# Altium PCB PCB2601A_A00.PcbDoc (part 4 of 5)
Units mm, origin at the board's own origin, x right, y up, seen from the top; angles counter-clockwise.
Board outline 30.4 x 51 mm, 8 copper layers (Top Layer, Signal Layer 2, Signal Layer 3, Signal Layer 4, Signal Layer 5, Signal Layer 6, Signal Layer 7, Bottom Layer), stack 1.492 mm thick; 194 components, 130 nets, 5039 pads, 478 vias.
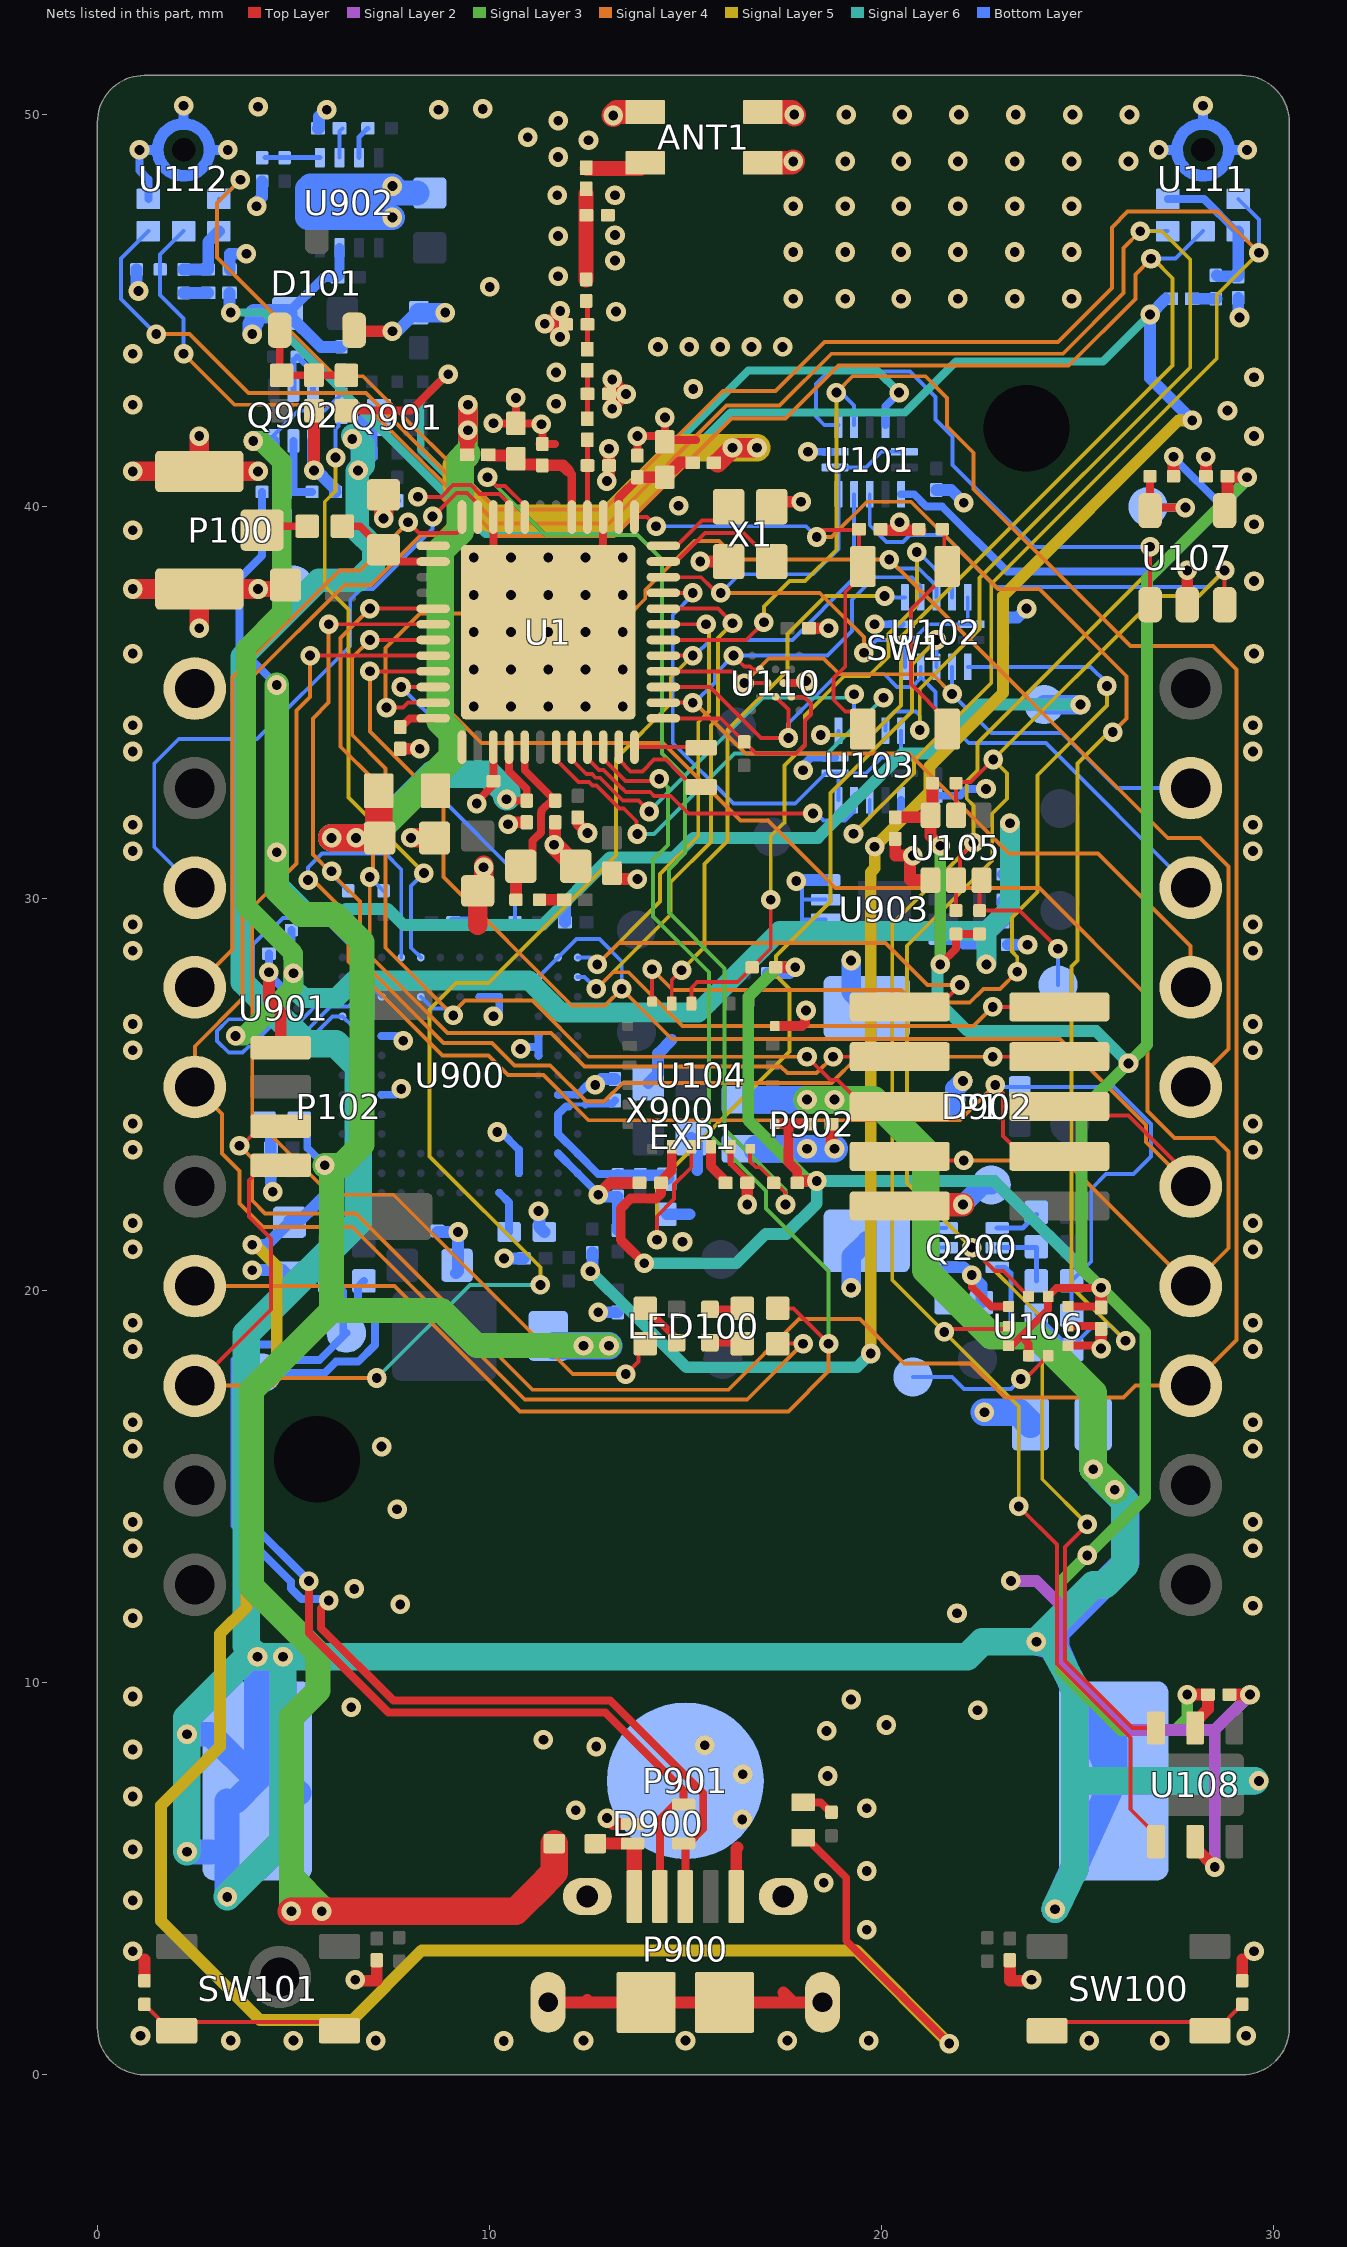
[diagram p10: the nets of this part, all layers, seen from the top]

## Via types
v1: diameter 0.5, hole 0.25, Top Layer to Bottom Layer, tented both sides, 478 vias

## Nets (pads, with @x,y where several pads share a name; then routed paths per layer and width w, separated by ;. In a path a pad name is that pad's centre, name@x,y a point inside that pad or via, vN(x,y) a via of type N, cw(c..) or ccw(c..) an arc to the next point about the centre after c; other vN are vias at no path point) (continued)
DBG_3V3: C914.1 C919.1 Q902.3 R906.2 R910.2 R911.2 R912.2 R929.2 R933.1 U901.A1 U901.E3 U903.8 | length 50.8
  Signal Layer 3 w0.5: v1(3.525,26.5) 3.75,26.5 5,27.75 v1(5,28.101) 5,28.6 3.8,29.8 3.8,36.4 4.7,37.3 4.7,41.15 4.175,41.675 v1(3.975,41.675)
  Signal Layer 6 w0.508: v1(5,28.101) 5,27.725 5.253,27.472 6.097,27.472 6.538,27.913 11.012,27.913 11.825,27.1 12.575,27.1 12.575,27.096 12.975,27.096 12.979,27.1 13.121,27.1 13.125,27.096 13.625,27.096 13.629,27.1 15.325,27.1 17.4,29.175 22.675,29.175 ; v1@22.675,28.35 22.675,29.175 ; v1(23.275,31.925) 23.275,29.775 22.675,29.175
  Bottom Layer w0.1: Q902.3@4.5,41.675 4.5,41.825 5.125,42.45 5.8,42.45 R929.2@6.225,42.875 R933.1@6.225,43.475
  Bottom Layer w0.2: C919.1@22.675,28.85 22.675,28.925 23.1,29.35 R912.2@23.1,29.4
  Bottom Layer w0.203: v1(3.525,26.5) 4.1,26.5 U901.E3@4.4,26.8 ; C914.1@4.925,28.6 4.963,28.562 4.963,28.139 v1(5,28.101) ; C914.1@4.945,28.625 4.95,28.63 R906.2@4.95,29.2 ; v1@5.025,28.126 5.1,28.052 U901.A1@5.1,27.6
  Bottom Layer w0.3: v1(3.975,41.675) Q902.3@4.5,41.675 ; U903.8@21.575,28.975 21.975,28.975 22.1,28.85 C919.1@22.525,28.85 ; v1(22.675,28.325) C919.1@22.675,28.825 ; R912.2@23.1,29.4 R911.2@23.1,29.95 ; R910.2@23.1,30.625 23.275,30.8 v1(23.275,31.925)
DBG_SPI_CS: R906.1 U900.B1 U900.B2 U901.A3 | length 5.6
  Bottom Layer w0.1: R906.1@4.35,29.1 4.36,29.1 4.469,29.209 R906.1@4.469,29.219 ; U901.A3@4.4,27.6 4.4,27.605 4.286,27.719 4.207,27.719 3.969,27.957 3.969,28.829 4.34,29.2 R906.1@4.35,29.2 4.459,29.309 4.534,29.309 4.737,29.512 5.738,29.512 U900.B1@6.75,28.5 U900.B2@6.75,28
DBG_SPI_MISO: U900.A4 U900.B3 U901.C3 | length 7.2
  Bottom Layer w0.1: U901.C3@4.4,27.2 4.125,26.925 3.35,26.925 3.05,26.625 3.05,26.375 3.35,26.075 3.7,26.075 3.85,26.225 5.225,26.225 6,27 U900.A4@6.25,27 6.5,26.75 6.925,26.75 7,26.825 7,27.25 U900.B3@6.75,27.5
DBG_SPI_MOSI: U900.C3 U901.D2 | length 3.6
  Bottom Layer w0.1: U901.D2@4.75,27 4.75,26.7 4.925,26.525 5.225,26.525 5.95,27.25 6.4,27.25 6.5,27.35 6.5,27.625 6.625,27.75 7,27.75 U900.C3@7.25,27.5
DBG_SPI_SCLK: U900.A3 U901.E1 | length 1.4
  Bottom Layer w0.1: U901.E1@5.1,26.8 5.8,27.5 U900.A3@6.25,27.5
DBG_USB_DM: D900.5 P900.2 R903.1 TPJ19.1 | length 26.8
  Top Layer w0.203: v1(5.395,12.595) 5.395,11.274 7.424,9.245 12.955,9.245 14.95,7.25 D900.5@14.95,6.9 14.725,6.9 14.345,6.52 P900.2@14.345,4.55
  Bottom Layer w0.203: v1(5.395,12.595) 3.805,14.186 3.805,17.505 TPJ19.1@4.2,17.9 5.797,17.9 6.088,18.191 6.652,18.191 7.079,18.618 7.079,19.222 6.642,19.659 6.642,20.092 R903.1@6.8,20.25
DBG_USB_DP: D900.4 P900.3 R904.1 TPJ18.1 | length 27.7
  Top Layer w0.203: v1(5.9,12.1) 5.7,11.9 5.7,11.4 7.55,9.55 13.081,9.55 15.453,7.178 15.453,6.278 15.075,5.9 D900.4@14.95,5.9 14.995,5.855 P900.3@14.995,4.55
  Bottom Layer w0.203: v1(5.9,12.1) 5.86,12.14 5.206,12.14 4.94,12.406 4.94,12.579 3.5,14.019 3.5,17.608 3.498,17.609 3.498,18.191 3.5,18.192 3.5,18.23 3.898,18.629 4.502,18.629 4.9,18.23 5.66,18.23 TPJ18.1@6.35,18.92 6.271,18.92 6.271,19.979 R904.1@6,20.25
DBG_VBUS: C901.1 D901.2 L901.2 R917.2 TPJ12.1 U900.A11 U900.B12 | length 86.7
  Top Layer w0.7: v1(4.95,4.175) v1(5.725,4.175) 10.675,4.175 11.42,4.92 11.42,4.933 11.65,5.163 L901.2@11.65,5.9
  Signal Layer 3 w0.635: v1(4.575,35.45) v1(4.575,31.183) 4.575,30.225 5.2,29.6 6.05,29.6 6.75,28.9 6.75,23.725 6.225,23.2 v1(5.8,23.2) ; v1(4.95,4.175) v1(5.725,4.175) ; v1@4.95,4.275 4.95,5.05 ; v1@5.725,4.275 4.95,5.05 ; v1@5.975,23.025 5.975,19.5 ; v1(13.05,18.6) v1(12.4,18.6) 9.675,18.6 8.775,19.5 5.975,19.5 ; 4.95,5.05 4.95,9.125 5.625,9.8 5.625,10.758 3.928,12.455 3.928,17.454 5.975,19.5
  Signal Layer 6 w0.305: v1(4.575,31.183) 4.575,30.542 5.538,29.578 6.178,29.578 6.339,29.739 7.402,29.739 7.816,29.325 11.35,29.325 13.075,31.05 14.7,31.05 15.2,31.55 18.375,31.55 20.525,33.7 21.275,33.7 22.525,34.95 v1(25.075,34.95)
  Bottom Layer w0.152: v1(5.8,23.2) 5.95,23.2 U900.A11@6.25,23.5 U900.B12@6.75,23
  Bottom Layer w0.2: R917.2@4.2,40.375 4.2,38.75 3.625,38.175 3.625,36.4 v1(4.575,35.45) ; C901.1@5.15,24.3 5.355,24.095 5.355,23.645 v1(5.8,23.2)
  Bottom Layer w0.5: TPJ12.1@24.15,34.95 v1(25.075,34.95)
  Bottom Layer w0.7: D901.2@11.65,18.6 v1(12.4,18.6) v1(13.05,18.6)
DBG_VREGO: C902.1 LED900.1 U900.A12 | length 51.6
  Top Layer w0.2: LED900.1@18,6.05 18.075,6.05 19.1,5.025 19.1,3.425 v1(21.726,0.799)
  Signal Layer 5 w0.3: v1@4,21.2 4.575,20.625 4.575,18.3 3.805,17.53 3.805,11.93 3.125,11.25 3.125,8.375 1.625,6.875 1.625,3.925 4.15,1.4 6.5,1.4 8.275,3.175 19.35,3.175 v1(21.726,0.799)
  Bottom Layer w0.2: 5.85,22.475 5.85,22.6 U900.A12@6.25,23
  Bottom Layer w0.3: v1(3.95,21.175) 4.325,21.175 C902.1@4.9,21.75 ; C902.1@4.9,21.8 5.175,21.8 5.4,22.025 5.407,22.025 5.7,22.318 5.7,22.325 5.85,22.475
DEBUG_PTI_DATA: P1.10 U1.7 U900.N1 | length 23.3
  Top Layer w0.1: U1.7@14.435,37 15.5,37 15.525,36.975 v1(15.525,37)
  Top Layer w0.102: P1.10@20.465,27.24 21.44,27.24 v1(22,27.8)
  Signal Layer 4 w0.1: v1(12.75,28.325) 13.3,28.875 20.1,28.875 21.175,27.8 v1(22,27.8)
  Signal Layer 5 w0.1: v1(12.75,28.325) 14.35,29.925 14.35,30.625 15.325,31.6 15.325,34.5 15.6,34.775 15.6,36.925 v1(15.525,37)
  Bottom Layer w0.1: U900.N1@12.25,28.5 12.575,28.5 v1(12.75,28.325)
DEBUG_PTI_FRAME: P1.9 U1.8 U900.N2 | length 26
  Top Layer w0.1: U1.8@14.435,37.4 15.825,37.4 v1(16.2,37.025) ; v1(22.835,27.24) P1.9@24.535,27.24
  Signal Layer 4 w0.1: v1(12.725,27.7) 13.15,28.125 13.55,28.125 14.925,26.75 22.345,26.75 v1(22.835,27.24)
  Signal Layer 5 w0.1: v1(12.725,27.7) 14.625,29.6 14.625,30.425 15.65,31.45 15.65,34.425 15.825,34.6 15.825,36.65 v1(16.2,37.025)
  Bottom Layer w0.1: U900.N2@12.25,28 12.425,28 v1(12.725,27.7)
DEBUG_RESET: D902.1 P1.3 R206.1 R209.1 U900.D1 | length 39.9
  Top Layer w0.1: v1(22.9,25.25) 23.1,25.05 23.1,23.95 23.62,23.43 P1.3@24.535,23.43
  Signal Layer 4 w0.1: v1(5.375,30.475) 5.5,30.475 6.4,29.575 6.4,28.4 8.8,26 9.975,26 10.475,25.5 11.375,25.5 12.525,24.35 22,24.35 v1(22.9,25.25)
  Bottom Layer w0.1: v1(5.375,30.475) 5.375,30.8 5.725,31.15 7.35,31.15 7.75,30.75 U900.D1@7.75,28.5 ; v1(22.9,25.25) 22.95,25.2 D902.1@23.525,25.2 25.925,25.2 26.875,24.25 26.875,23.425 26.425,22.975 25.725,22.975 25.35,22.6 25.35,20.75 R206.1@24.85,20.25 R209.1@24.85,19.4
DEBUG_SWCLK: P1.8 R920.2 U1.29 | length 26.6
  Top Layer w0.1: v1(6.95,37.4) U1.29@8.565,37.4 ; v1(18.765,25.97) P1.8@20.465,25.97
  Signal Layer 4 w0.1: v1(6.95,37.4) 6.2,36.65 6.2,33.875 7.025,33.05 7.025,30.632 v1(6.946,30.554) 6.946,28.554 8.925,26.575 11.575,26.575 12.425,25.725 17.425,25.725 17.6,25.55 18.345,25.55 v1(18.765,25.97)
  Bottom Layer w0.1: v1(6.946,30.554) R920.2@7.3,30.2
DEBUG_SWDIO: P1.7 R919.2 U1.30 | length 32.3
  Top Layer w0.1: v1(5.9,37) U1.30@8.565,37 ; v1(22.835,25.97) P1.7@24.535,25.97
  Signal Layer 4 w0.1: v1(5.9,37) 5.9,35 5.5,34.6 5.5,31.125 5.975,30.65 6.7,29.925 6.7,28.45 8.825,26.325 10.064,26.325 10.639,25.75 11.55,25.75 12.475,24.825 12.925,24.825 13.4,25.3 18.725,25.3 19.395,25.97 v1(22.835,25.97)
  Bottom Layer w0.1: v1@5.975,30.65 5.975,30.625 R919.2@6.4,30.2
  other v1: 5.975,30.7
DEBUG_SWO: P1.6 U1.31 U900.E3 | length 26.3
  Top Layer w0.1: v1@6.825,36.6 U1.31@8.565,36.6 ; v1(18.1,25.97) 18.695,25.375 18.875,25.375 19.55,24.7 P1.6@20.465,24.7
  Signal Layer 4 w0.1: v1(6.95,36.6) 6.5,36.15 6.5,34.175 7.35,33.325 7.35,28.75 v1@9.037,27.063 ; v1(9.075,27.025) v1@9.037,27.063 ; v1(18.1,25.97) 12.53,25.97 11.094,27.406 9.381,27.406 v1@9.037,27.063
  Bottom Layer w0.1: U900.E3@8.25,27.5 8.555,27.195 8.905,27.195 v1(9.075,27.025)
EFR32_AIN0: C130.1 R129.2 U1.26 | length 2.7
  Top Layer w0.2: R129.2@6.25,39.5 6.7,39.5 C130.1@7.3,38.9 7.6,38.6 U1.26@8.565,38.6
EFR32_AIN1: U1.25
EFR32_AIN2: EXP1.7 U1.24 | length 16.2
  Top Layer w0.1: v1(7.925,39.6) 8.2,39.325 9.175,39.325 9.3,39.45 U1.24@9.3,39.735
  Signal Layer 4 w0.1: EXP1.7@2.486,27.74 3.45,28.704 3.45,35.65 6.175,38.375 6.7,38.375 v1(7.925,39.6)
EFR32_AIN3: EXP1.5 U1.23 | length 16
  Top Layer w0.1: v1@8.556,39.744 9.163,40.35 9.425,40.35 9.7,40.075 U1.23@9.7,39.735
  Bottom Layer w0.1: EXP1.5@2.486,30.28 1.45,31.316 1.45,33.45 2.075,34.075 4.075,34.075 6.45,36.45 6.45,37.625 6.725,37.9 7.025,37.9 8.55,39.425 v1(8.55,39.75)
EFR32_PA04: R135.2 U1.32 | length 28.7
  Top Layer w0.1: v1(5.425,36.2) U1.32@8.565,36.2 ; v1(13.475,17.875) 13.8,18.2 13.8,18.45 R135.2@14,18.65
  Signal Layer 4 w0.1: v1(5.425,36.2) 5.425,35.15 5.075,34.8 5.075,30.9 3.95,29.775 3.95,24.45 5.95,22.45 7.55,22.45 12.125,17.875 v1(13.475,17.875)
EFR32_PA05: EXP1.12 P1.5 U1.33 U900.L2 U900.M1 | length 38.4
  Top Layer w0.1: v1(6.95,35.8) U1.33@8.565,35.8 ; P1.5@24.535,24.7 25.5,24.7 25.725,24.475 26.071,24.475 26.3,24.475 27.886,22.889 EXP1.12@27.886,22.66
  Signal Layer 4 w0.1: v1(6.95,35.8) 6.95,34.263 8.825,32.388 8.825,30.55 12.1,27.275 12.95,27.275 v1(13.375,27.7) 14.65,26.425 24.55,26.425 26.75,24.225 26.75,23.796 EXP1.12@27.886,22.66
  Bottom Layer w0.1: U900.L2@11.25,28 U900.M1@11.75,28.5 12.218,28.968 12.807,28.968 13.375,28.4 v1(13.375,27.7)
EFR32_PA06: EXP1.14 P1.4 R921.2 U1.34 | length 48.4
  Top Layer w0.1: v1(7.75,35.4) U1.34@8.565,35.4
  Top Layer w0.102: P1.4@20.465,23.43 20.57,23.325 v1(22.1,23.325)
  Signal Layer 4 w0.1: v1(7.75,35.4) 8.375,35.4 9.8,33.975 14.425,33.975 16.4,32 17.1,32 18.825,30.275 24.025,30.275 26.788,27.512 26.788,24.587 27.475,23.9 28.5,23.9 28.85,23.55 28.85,21.084 EXP1.14@27.886,20.12 24.681,23.325 v1(22.1,23.325)
  Bottom Layer w0.102: v1(7.75,35.4) 8.8,34.35 8.8,32.525 10.65,30.675 R921.2@10.65,29.4
EFR32_PA07: EXP1.10 U1.35 U102.10 | length 36.8
  Top Layer w0.1: v1(7.375,34.875) 7.8,34.875 7.925,35 U1.35@8.565,35
  Signal Layer 4 w0.1: v1(7.375,34.875) 7.35,34.9 7.35,36.4 8.225,37.275 13.6,37.275 13.975,37.65 13.975,37.875 15.225,39.125 15.85,39.125 16.325,38.65 v1(20.2,38.65) 27.3,31.55 28.125,31.55 28.85,30.825 28.85,26.164 EXP1.10@27.886,25.2
  Bottom Layer w0.1: v1(20.2,38.65) 20.425,38.425 20.95,38.425 21.4,37.975 U102.10@21.4,37.685
EFR32_PB00: EXP1.9 R136.2 U1.21 | length 43.3
  Top Layer w0.1: v1(8.175,40.25) 8.775,40.25 9.075,40.55 9.525,40.55 9.75,40.325 10.25,40.325 10.5,40.075 U1.21@10.5,39.735 ; R136.2@17.35,18.65 v1(18,18.65)
  Signal Layer 4 w0.1: v1(8.175,40.25) 8.775,40.25 9.075,39.95 9.075,39.65 8.7,39.275 8.25,39.275 6.975,38 6.3,38 3.9,35.6 3.9,30.175 3.7,29.975 3.7,27.45 2.486,26.236 EXP1.9@2.486,25.2 3.175,24.511 3.175,23.5 3.625,23.05 3.625,22.225 4.225,21.625 6.5,21.625 10.9,17.225 16.575,17.225 v1(18,18.65)
EFR32_PB01: R103.2 U1.20 U104.12 | length 26.8
  Top Layer w0.1: v1(9.95,40.75) 10.175,40.525 10.4,40.525 10.9,40.025 U1.20@10.9,39.735 ; U104.12@16.65,23.625 16.65,23.3 16.8,23.15 16.9,23.15 17.55,22.5 v1(17.55,22.2)
  Signal Layer 3 w0.1: v1(9.95,40.75) 11.425,39.275 13.775,39.275 14.4,38.65 14.4,33.7 14.988,33.112 14.988,31.163 14.575,30.75 14.575,29.65 16,28.225 16,24.125 17.55,22.575 v1(17.55,22.2)
EFR32_PC00: R100.2 U1.1 U110.B4 | length 5.8
  Top Layer w0.1: U1.1@14.435,34.6 15.9,34.6 R100.2@16.5,34 16.8,33.7 17.825,33.7 18.05,33.925 18.05,34.55 18.2,34.7 18.2,34.975 18.025,35.15 U110.B4@17.7,35.15
EFR32_PC01: EXP1.8 U1.2 U102.9 U110.F2 | length 26
  Top Layer w0.1: U1.2@14.435,35 v1@15.235,35 ; v1(16.225,36.2) 16.5,35.925 16.65,35.925 16.725,35.85 U110.F2@16.9,35.85
  Signal Layer 4 w0.1: v1@15.235,35 16.535,33.7 20.7,33.7 23.25,31.15 25.525,31.15 27.886,28.789 EXP1.8@27.886,27.74
  Bottom Layer w0.1: v1@15.235,35 15.75,35.515 15.75,35.725 v1(16.225,36.2) 18.625,36.2 19.25,36.825 19.25,37.625 19.825,38.2 20.775,38.2 21,37.975 U102.9@21,37.685
  other v1: 15.185,35
EFR32_PC02: EXP1.6 U1.3 U102.4 U110.D4 | length 18.9
  Top Layer w0.1: U1.3@14.435,35.4 15.625,35.4 16.925,34.1 v1(17.625,34.1) ; U110.D4@17.3,35.15 17.625,34.825 v1@17.625,34.225
  Bottom Layer w0.1: v1(17.625,34.1) 17.625,34.475 18.875,35.725 20.075,35.725 20.4,35.4 20.775,35.4 21,35.625 U102.4@21,35.65 ; U102.4@21,35.915 U102.4@21,35.65 ; EXP1.6@27.886,30.28 24.191,33.975 22.225,33.975 21.375,34.825 21.375,35.275 U102.4@21,35.65
EFR32_PC03: EXP1.4 U1.4 U102.2 U110.E3 | length 16.5
  Top Layer w0.1: U1.4@14.435,35.8 16.2,35.8 v1(16.5,35.5) U110.E3@17.1,35.5
  Signal Layer 4 w0.1: v1(16.5,35.5) 17.125,36.125 18.525,36.125 18.925,35.725 21.3,35.725 v1(21.8,35.225)
  Bottom Layer w0.1: U102.2@21.8,35.915 v1(21.8,35.225) 22.8,34.225 24.6,34.225 26.005,32.82 EXP1.4@27.886,32.82
EFR32_PC04: EXP1.15 P102.4 U1.5 U101.4 | length 45.4
  Top Layer w0.1: EXP1.15@2.486,17.58 4.425,19.519 4.425,21.334 3.863,21.896 3.863,22.813 4.25,23.2 P102.4@4.675,23.2 ; U1.5@14.435,36.2 v1(15.185,36.2) v1@15.235,36.2
  Signal Layer 4 w0.1: EXP1.15@2.486,17.58 4.48,17.58 4.675,17.775 v1(7.125,17.775)
  Signal Layer 5 w0.1: v1(11.3,20.15) 11.3,20.6 8.475,23.425 8.475,27.175 9.15,27.85 9.975,27.85 13.225,31.1 13.225,33.575 14.625,34.975 14.625,35.64 v1(15.185,36.2)
  Signal Layer 6 w0.1: v1(7.125,17.775) 9.5,20.15 v1(11.3,20.15)
  Bottom Layer w0.1: v1@15.235,36.2 15.635,36.6 17.725,36.6 19.3,38.175 U101.4@19.3,40.315
EFR32_PC05: EXP1.16 P102.3 U1.6 U101.9 | length 74.3
  Top Layer w0.1: v1(3.625,23.7) 3.675,23.7 4.175,24.2 P102.3@4.675,24.2 ; U1.6@14.435,36.6 16.55,36.6 v1(17,37.05)
  Signal Layer 4 w0.1: v1(3.625,23.7) 3.95,23.375 3.95,22.3 4.275,21.975 6.6,21.975 11.1,17.475 16.1,17.475 17.9,19.275 19.45,19.275 20.575,18.15 22.275,18.15 23.15,17.275 26.175,17.275 26.48,17.58 EXP1.16@27.886,17.58 29.05,18.744 29.05,35.85 28.45,36.45 26.35,36.45 22.35,40.45 22.35,41.375 21.675,42.05 21.675,42.775 21.125,43.325 19.265,43.325 v1(18.85,42.91)
  Signal Layer 5 w0.1: v1(17,37.05) 17,37.45 17.65,38.1 18.05,38.1 18.85,38.9 v1(18.85,42.91)
  Bottom Layer w0.1: v1(18.85,42.91) 18.965,42.91 19.3,42.575 U101.9@19.3,42.085
EFR32_PC08: U1.9 U103.5 U103.6 U103.12 U103.13 | length 13.3
  Top Layer w0.1: U1.9@14.435,37.8 v1@15.235,37.8
  Bottom Layer w0.1: v1@15.235,37.8 14.675,37.24 14.675,33.975 16.225,32.425 17.8,32.425 18.575,33.2 U103.6@18.815,33.2 ; U103.5@18.9,32.515 18.9,33.115 U103.6@18.815,33.2 ; U103.12@20.5,34.285 20.5,33.685 U103.13@20.585,33.6 20,33.6 19.6,33.2 U103.6@18.815,33.2
  other v1: 15.185,37.8
EFR32_PC09: U1.10 U101.5 U101.6 U101.13 U102.5 U102.6 U102.12 U102.13 | length 18.1
  Top Layer w0.1: U1.10@14.435,38.2 15.401,38.2 15.635,37.966 ; 15.635,37.965 15.8,37.8 v1(15.9,37.8)
  Signal Layer 4 w0.1: v1(15.9,37.8) 18.425,37.8 19.55,36.675 v1(19.55,36.275)
  Bottom Layer w0.1: v1(15.9,37.8) 16.375,38.275 18.25,38.275 18.9,38.925 U101.5@18.9,40.315 18.9,40.915 U101.6@18.815,41 19.6,41 20,41.4 U101.13@20.585,41.4 ; v1(19.55,36.275) 19.875,36.6 U102.6@20.515,36.6 ; U102.5@20.6,35.915 20.6,36.515 U102.6@20.515,36.6 ; U102.12@22.2,37.685 22.2,37.085 U102.13@22.285,37 21.2,37 20.8,36.6 U102.6@20.515,36.6
EFR32_PD00: U1.48 X2.1 | length 1.7
  Top Layer w0.1: U1.48@13.7,33.865 15.385,33.865 X2.1@15.4,33.85
EFR32_PD01: U1.47 X2.2 | length 3
  Top Layer w0.1: U1.47@13.3,33.865 13.3,33.55 13.6,33.25 13.9,33.25 14.2,33.55 14.5,33.55 14.8,33.25 15.2,32.85 X2.2@15.4,32.85
EFR32_PD02: EXP1.13 R137.2 U1.46 | length 38.8
  Top Layer w0.1: U1.46@12.9,33.865 12.9,33.575 13.468,33.007 14.283,33.007 v1(14.332,33.056) ; R137.2@17.35,19.55 17.75,19.55 v1(18.65,18.65)
  Signal Layer 3 w0.1: v1(14.332,33.056) 14.55,32.838 14.55,31.375 14.175,31 14.175,29.55 15.6,28.125 15.6,24 17.05,22.55 17.05,22.1 18.65,20.5 v1(18.65,18.65)
  Signal Layer 4 w0.1: EXP1.13@2.486,20.12 7.58,20.12 10.775,16.925 17.625,16.925 18.65,17.95 v1(18.65,18.65)
EFR32_PD03: U1.45 U103.4 | length 8.1
  Top Layer w0.1: U1.45@12.5,33.865 12.5,33.577 12.792,33.285 12.907,33.285 13.385,32.807 13.393,32.807 13.476,32.724 14.101,32.724 14.2,32.625 14.625,32.625 15.075,32.175 v1(18.25,32.175)
  Bottom Layer w0.1: v1(18.25,32.175) 18.35,32.175 18.525,32 19.075,32 19.3,32.225 U103.4@19.3,32.515
EFR32_PD04: U1.44 U103.9 | length 10.2
  Top Layer w0.1: U1.44@12.1,33.865 12.1,33.55 12.47,33.18 12.614,33.18 12.709,33.085 12.815,33.085 13.4,32.5 13.8,32.5 v1(14.075,32.225)
  Signal Layer 6 w0.1: v1(14.075,32.225) 16.975,35.125 19.209,35.125 v1(19.3,35.216)
  Bottom Layer w0.1: U103.9@19.3,34.285 v1(19.3,35.216)
EFR32_PD05: U1.43 U103.10 | length 12.1
  Top Layer w0.1: U1.43@11.7,33.865 11.7,33.55 12.275,32.975 12.537,32.975 12.627,32.885 12.732,32.885 13.317,32.3 13.425,32.3 13.75,31.975 v1@13.75,31.65
  Signal Layer 6 w0.1: v1@13.75,31.65 14.2,31.65 16.25,33.7 18.625,33.7 v1(20.05,35.125)
  Bottom Layer w0.1: U103.10@19.7,34.285 19.7,34.775 v1(20.05,35.125)
  other v1: 13.775,31.65
EFR32_RESET: C1.1 R209.2 R212.2 SW1.1 SW1.2 U1.13 | length 43.3
  Top Layer w0.1: U1.13@13.7,39.735 14.015,39.735 v1(14.25,39.5) ; v1(18.35,39.225) 18.525,39.4 19.425,39.4 19.425,38.575 SW1.2@19.525,38.475 19.525,38.275 19.075,37.825 19.075,35.925 18.775,35.625 18.775,35.075 19.075,34.775 19.3,34.775 19.525,34.55 SW1.1@19.525,34.325
  Signal Layer 4 w0.1: v1(18.35,39.225) 18.725,39.225 19.625,40.125 20.75,40.125 22.975,37.9 24.025,37.9 26.25,35.675 26.25,34.6 v1(25.9,34.25)
  Signal Layer 5 w0.102: v1(25.9,34.25) 25.8,34.25 25,33.45 25,28.425 24.85,28.275 24.85,20.1 v1(26.225,18.725)
  Bottom Layer w0.1: v1(14.25,39.5) 18.075,39.5 v1(18.35,39.225) v1@18.425,39.15
  Bottom Layer w0.102: R209.2@23.95,19.4 24.8,18.55 24.85,18.55 25.4,19.1 25.85,19.1 v1(26.225,18.725)
GND: ANT1.2 ANT1.3 ANT1.4 C1.2 C3.2 C4.2 C5.2 C6.2 C7.2 C8.2 C9.2 C11.2 C12.2 C13.2 C14.2 C15.2 C17.2 C18.2 C19.2 C20.2 C21.2 C22.2 C23.2 C24.2 C101.2 C104.2 C105.2 C106.2 C110.2 C111.2 C113.2 C114.2 C115.2 C117.2 C130.2 C142.2 C145.2 C154.2 C156.2 C900.2 C901.2 C902.2 C903.2 C904.2 C905.2 C907.2 C908.2 C909.2 C910.2 C911.2 C914.2 C915.2 C916.2 C917.2 C918.2 C919.2 C920.2 C921.2 C923.2 C924.2 C925.2 C926.2 D101.2 D900.2 D902.3 EXP1.1 P1.2 P100.2 P100.3 P102.1 P900.5 P900.6 P900.7 P900.8 P900.9 P900.10 P900.11 P901.2 P902.1 P902.3 P902.4 Q200.1 Q902.1 R1.1 R141.2 R144.2 R150.2 R208.1 R909.1 R915.1 R916.1 R933.2 TPJ13.1 U1.0 U1.15 U1.22 U1.39 U101.7 U102.7 U103.7 U104.11 U104.18 U105.1 U106.3 U106.8 U106.9 U107.2 U108.2 U110.C3 U111.3 U112.2 U112.3 U900.C5 U900.C8 U900.H3 U900.J3 U900.K11 U900.K12 U900.L5 U900.L6 U900.M8 U900.M11 U900.N8 U900.N12 U901.B2 U902.3 U902.9 U903.1 U903.2 U903.3 U903.4 X1.2 X1.4 X900.2 X900.4 | length 155.3
  Top Layer w0.15: U104.11@16.15,23.747 U104.11@16.15,23.675 16.15,23.25 16.575,22.825 C106.2@16.575,22.8
  Top Layer w0.2: v1(9.675,32.425) 9.675,32.475 10.1,32.9 C9.2@10.1,33 U1.39@10.1,33.865 ; U1.0@10.1,35.4 v1(11.5,36.8) ; U1.22@10.1,39.735 10.1,38.2 v1(10.55,37.75) v1(11.5,36.8) ; v1(10.1,42.125) C18.2@10.675,42.125 ; v1(10.675,42.775) C18.2@10.675,42.125 ; C19.2@11.275,41.6 C19.2@11.35,41.6 ; v1@11.275,42.075 11.225,42.125 C18.2@10.675,42.125 ; v1@11.35,42.075 C19.2@11.35,41.6 ; 11.675,41.6 C19.2@11.35,41.6 ; U1.15@12.9,39.735 12.9,38.2 v1(11.5,36.8) ; C12.2@13.775,41.3 v1(13.775,41.8) ; v1@13.825,41.8 14.325,41.8 C11.2@14.475,41.65 ; v1(14.475,42.275) C11.2@14.475,41.65 ; 15.275,41.7 14.525,41.7 C11.2@14.475,41.65 ; U110.C3@17.5,35.5 18.025,35.5 v1(18.075,35.55) ; v1(22.3,20.4) 22.3,20.1 22.8,19.6 U106.3@23.243,19.6 ; U106.8@24.758,18.6 25.525,18.6 v1(25.6,18.525) ; U106.9@24.758,19.1 25.525,19.1 C111.2@25.6,19.025
  Top Layer w0.203: ANT1.4@13.972,49.978 ANT1.4@13.986,49.978
  Top Layer w0.25: v1@11.453,44.72 11.543,44.72 11.686,44.72 11.756,44.65 11.805,44.65 11.874,44.65 11.805,44.718 v1(11.805,44.991) ; v1(11.799,44.33) 11.799,44.374 11.799,44.388 11.799,44.575 C5.2@11.874,44.649 ; C5.2@11.874,44.65 11.953,44.65 C5.2@11.981,44.65 ; C4.2@13.025,42.87 C4.2@13.132,42.87 ; v1(13.132,42.495) 13.132,42.743 C4.2@13.132,42.87 ; v1(13.132,43.245) 13.132,43.057 13.132,42.978 C4.2@13.132,42.87 ; v1(13.482,42.87) 13.24,42.87 C4.2@13.132,42.87 ; U104.18@17.375,26.75 17.975,26.75 18.05,26.825 18.05,27.125 v1(18.075,27.15)
  Top Layer w0.3: R144.2@1.2,2.4 1.2,2.95 ; v1(4.375,28.125) 4.375,27.4 4.675,27.1 P102.1@4.675,26.2 ; C115.2@5.5,42.45 5.525,42.425 v1(5.525,40.925) ; D101.2@6.55,44.5 6.575,44.475 v1(7.525,44.475) v1@7.575,44.475 ; v1(6.575,2.425) 6.6,2.4 7.125,2.4 C145.2@7.125,2.925 ; C17.2@7.725,33.825 v1(8.225,33.825) ; v1(10.475,31.9) 10.525,31.95 C13.2@10.95,31.95 ; P900.8@11.495,1.85 12.425,1.85 ; v1@11.6,31.425 11.675,31.5 C21.2@11.675,31.95 ; v1@11.756,44.995 v1@11.781,45.02 ; v1(11.799,44.33) 11.843,44.33 11.799,44.374 v1@11.792,44.381 ; v1(11.805,44.991) v1@11.805,44.996 ; C5.2@11.874,44.649 11.874,44.462 11.799,44.388 v1@11.792,44.381 ; C5.2@11.874,44.65 11.874,44.928 11.825,44.976 11.808,44.993 v1@11.805,44.996 ; C15.2@12.25,32.075 12.25,31.925 v1(12.5,31.675) ; 12.495,1.92 12.425,1.85 ; v1(12.776,22.451) 13.075,22.75 C104.2@13.825,22.75 ; v1@13.025,40.675 13.05,40.7 C3.2@13.05,41.05 13.05,41.45 v1@13.075,41.475 ; C4.2@13.025,42.85 13.132,42.743 v1@13.243,42.632 ; C14.2@13.125,30.65 13.275,30.5 v1(13.775,30.5) ; v1@13.167,43.242 13.167,43.185 v1@13.175,43.177 ; C4.2@13.175,42.937 v1@13.175,43.1 ; v1@13.218,43.275 v1@13.175,43.232 ; v1@13.25,42.861 13.24,42.87 13.174,42.936 13.132,42.978 13.125,42.986 13.037,42.898 13.037,42.962 13.132,43.057 v1@13.175,43.1 ; v1@13.25,43.175 v1@13.241,43.166 ; v1@13.327,43.001 13.359,42.97 v1@13.379,42.974 ; v1@13.425,42.982 v1@13.379,42.974 ; v1(13.482,42.87) v1@13.243,42.632 ; v1(13.482,42.87) v1@13.379,42.974 ; v1(15.375,38.6) X1.2@16.1,38.6 ; P900.5@16.295,4.55 16.295,5.77 16.325,5.8 ; v1@16.575,22.25 16.575,22.3 C106.2@16.575,22.75 C106.2@16.575,22.8 ; X1.4@17.2,40 17.325,40.125 v1(17.95,40.125) ; 17.495,2.105 17.75,1.85 ; C101.2@18.15,36.9 v1(18.65,36.9) v1@18.75,36.9 ; P900.9@18.495,1.85 17.75,1.85 ; C105.2@18.725,24.25 18.725,23.7 v1(18.8,23.625) ; C1.2@19.975,39.4 R1.1@21,39.4 ; C110.2@20.35,31.525 20.35,31.1 v1(20.8,31.1) 20.725,31.025 20.725,30.475 U105.1@21.25,30.475 ; C142.2@23.275,2.925 23.275,2.4 23.8,2.4 v1(23.825,2.425) ; v1(25.6,18.525) C111.2@25.6,19.025 ; U107.2@27.8,37.5 v1(27.8,38.375) ; U108.2@28,5.95 28,5.8 v1(28.5,5.3) ; C113.2@28.275,40.775 v1(28.275,41.275) ; C114.2@28.875,9.7 v1(29.4,9.7) ; R141.2@29.2,2.4 29.2,2.95 ; v1@11.756,44.417 11.756,44.65 11.756,44.933 11.543,44.72 11.498,44.675 v1@11.756,44.417 ; v1@11.756,44.417 11.756,44.345 11.77,44.359 v1@11.792,44.381 ; v1@11.756,44.417 v1@11.792,44.381 ; v1@11.781,45.02 11.786,45.025 11.805,45.005 v1@11.805,44.996 ; v1@11.781,45.02 v1@11.805,44.996 ; 12.425,1.85 P900.10@13.995,1.85 P900.11@15.995,1.85 17.75,1.85 ; v1@13.175,43.1 v1@13.214,43.139 ; v1@13.175,43.1 v1@13.175,43.177 ; v1@13.175,43.177 v1@13.175,43.232 ; v1@13.175,43.177 v1@13.214,43.139 ; v1@13.175,43.232 v1@13.241,43.166 ; v1@13.214,43.139 v1@13.241,43.166 ; v1@13.214,43.139 13.264,43.089 v1@13.379,42.974 ; v1@13.243,42.632 13.25,42.625 13.236,42.625 v1@13.243,42.632
  Top Layer w0.305: v1(13,6.55) 13.15,6.4 D900.2@13.65,6.4
  Top Layer w0.4: v1(4.1,37.9) 4.7,37.9 C117.2@4.8,38 4.9,38 C117.2@5,38.1
  Top Layer w0.5: v1(0.9,37.9) P100.3@2.6,37.9 ; v1(0.9,40.9) P100.2@2.6,40.9 ; v1(2.6,36.9) P100.3@2.6,37.9 ; v1(2.6,41.8) P100.2@2.6,40.9 ; v1(4.1,37.9) P100.3@2.6,37.9 ; v1(4.1,40.9) P100.2@2.6,40.9 ; v1(7.3,39.7) C130.2@7.3,40.3 ; v1(8,31.55) C7.2@8.6,31.55 ; 9.7,29.325 C8.2@9.7,30.2 C8.2@9.7,30.275 ; C8.2@9.85,30.25 v1(9.85,30.8) v1@9.85,30.85 ; v1(11.65,31.375) C20.2@12.2,30.825
  Top Layer w0.6: v1(13.156,49.978) 13.244,50.066 ANT1.4@13.972,50.066 ; ANT1.2@16.972,48.766 17.711,48.766 v1(17.751,48.806) ; ANT1.3@16.972,50.066 17.709,50.066 v1(17.775,50) ; P1.2@20.465,22.16 20.505,22.2 v1(22.075,22.2)
  Signal Layer 2 w0.3: v1(23.3,12.6) 23.95,12.6 24.575,11.975 24.575,10.525 26.3,8.8 28.5,8.8 ; v1(28.5,5.3) 28.5,8.8 ; v1(29.4,9.7) 28.5,8.8
  Bottom Layer w0.1: v1(17.825,30.45) 17.975,30.3 17.975,30 ; U903.1@18.575,28.975 18.075,28.975 17.975,29.075 17.975,29.475 ; U903.2@18.575,29.475 17.975,29.475 ; U903.3@18.575,29.975 18,29.975 17.975,30 ; 17.975,29.475 17.975,30
  Bottom Layer w0.2: v1(1.075,49.1) 1.075,48.575 1.3,48.35 1.3,48.25 U112.2@1.3,47.848 ; U900.C8@7.25,25 7.6,25 v1(7.75,25.15) ; U900.C5@7.25,26.5 7.675,26.5 v1(7.8,26.375) ; v1(7.3,39.7) 7.3,40.15 R915.1@7.65,40.15 ; U900.H3@9.75,27.5 U900.J3@10.25,27.5 10.25,27.125 v1@10.125,27 ; v1@10.15,24.05 v1(10.2,24.05) 10.3,24.05 10.75,23.6 U900.K11@10.75,23.5 U900.K12@10.75,23 ; v1@10.795,26.22 11.22,26.22 11.25,26.25 ; U900.L6@11.25,26 11.25,26.25 ; U900.L5@11.25,26.5 11.25,26.25 ; U900.M11@11.75,23.5 U900.N12@12.25,23 12.774,22.476 v1(12.776,22.451) ; U900.M8@11.75,25 U900.N8@12.25,25 12.5,25.25 v1(12.7,25.25) ; v1(18,33.275) 18,33.4 18.2,33.6 U103.7@18.815,33.6 ; v1(18.125,41.4) U101.7@18.815,41.4 ; v1(19.825,37) U102.7@20.515,37 ; C24.2@21.4,32.625 22,32.625 22.175,32.8 22.65,32.8 v1(22.666,32.8)
  Bottom Layer w0.203: C914.2@4.375,28.6 v1(4.375,28.125) 4.375,28.075 4.75,27.7 U901.B2@4.75,27.4
  Bottom Layer w0.25: v1(1.075,49.1) 1.538,49.1 ; U112.3@2.2,49.762 v1(2.2,50.225) ; 2.862,49.1 v1(3.325,49.1) ; C915.2@4.85,44.925 5.775,45.85 C916.2@6.125,45.85 6.175,45.9 U902.3@6.175,46.6 ; v1(27.075,49.1) 27.538,49.1 ; U111.3@28.2,49.762 v1(28.2,50.225) ; 28.862,49.1 v1(29.325,49.1)
  Bottom Layer w0.3: v1@1,45.5 R150.2@1,46.05 ; C154.2@3.375,46.05 3.375,46.45 v1(3.8,46.45) ; v1(4.061,47.66) 4.061,47.761 4.2,47.9 R909.1@4.2,48.3 ; C901.2@4.25,24.325 4.425,24.15 C910.2@4.425,23.65 C926.2@4.425,23.05 v1@4.425,22.75 ; v1@7.575,44.475 7.65,44.475 8.125,44.95 C920.2@8.2,44.95 ; C911.2@8.675,21.5 v1(9.2,21.5) 9.2,20.5 C907.2@9.15,20.45 ; C908.2@9.075,29.4 9.5,29.4 ; v1(10.375,20.825) C923.2@10.875,20.825 ; 11.9,29.95 11.925,29.925 C925.2@11.925,29.4 ; v1(12.7,25.25) 12.85,25.4 C905.2@13.2,25.4 ; v1@12.725,19.45 v1(12.775,19.45) C909.2@13.275,19.45 ; v1(12.776,22.451) 12.827,22.4 C904.2@13.275,22.4 C924.2@13.275,21.55 ; X900.2@14.05,25.3 14.3,25.55 14.3,26.05 14.65,26.4 ; C903.2@14.525,21.95 15.1,21.95 ; X900.4@15.15,23.9 15.3,23.75 15.3,23.075 ; v1(17.825,30.45) 17.85,30.475 U903.4@18.575,30.475 ; C22.2@21.4,40.425 21.775,40.425 v1(22.1,40.1) ; Q200.1@21.65,20.6 22.1,20.6 v1(22.3,20.4) 22.55,20.15 R208.1@22.55,19.7 ; v1@22.625,32.825 v1@22.65,32.8 ; C23.2@23.1,37.175 23.475,37.175 v1(23.7,37.4) ; C919.2@23.225,28.825 v1(23.725,28.825) ; v1@29.1,44.855 C156.2@29.1,45.325
  Bottom Layer w0.305: v1(3.95,20.525) 4.725,20.525 C902.2@4.9,20.35 ; C915.2@4.85,44.925 5.7,44.075 R933.2@6.225,44.075 ; Q902.1@5.5,41.675 5.5,41.016 6.057,40.458 6.057,40.383 R916.1@6.065,40.375 ; C918.2@5.625,49.65 5.645,49.65 5.653,49.658 5.653,49.948 5.85,50.145 v1@5.85,50.2 ; R916.1@6.057,40.367 R916.1@6.065,40.375 ; R916.1@6.075,40.375 R916.1@6.065,40.375 ; v1(11.25,22.032) 11.268,22.05 11.3,22.05 11.275,22.025 11.275,21.625 C900.2@11.4,21.5
  Bottom Layer w0.5: v1(3.95,44.4) 3.95,44.651 4,44.701 4,44.925 C915.2@4.85,44.925 ; C920.2@8.2,44.95 v1@8.775,44.95 ; v1(19.225,20.075) 19.225,20.875 P902.4@19.625,21.275 ; v1(19.225,28.425) 19.225,27.625 P902.3@19.625,27.225 ; D902.3@21.875,24.7 21.875,25.15 v1(22.075,25.35) ; v1(22.075,22.2) 22.575,22.7 TPJ13.1@22.8,22.7
  Bottom Layer w0.635: 5.354,48.1 5.357,48.103 ; v1(7.525,47.375) U902.9@6.8,47.375 ; C917.2@8.15,48 v1@7.7,48 ; 5.357,47.382 5.725,47.75 U902.9@6.425,47.75 ; 5.357,47.382 5.365,47.375 U902.9@6.8,47.375 ; 5.357,47.382 5.357,48.103 ; 5.357,48.103 5.429,48.175 U902.9@6.85,48.175 ; U902.9@6.425,47.75 U902.9@6.8,47.375 ; U902.9@6.425,47.75 U902.9@6.675,48 ; U902.9@6.675,48 v1@7.7,48 ; U902.9@6.675,48 U902.9@6.85,48.175 ; U902.9@6.85,48.175 v1(7.525,48.175) v1@7.7,48
  Bottom Layer w0.7: P902.1@16.825,23.625 v1(18.1,23.625) v1(18.8,23.625) ; v1(22.625,16.9) 23.5,16.9 C921.2@23.8,16.6
  other v1: 10.363,0.864 3.4,0.875 5,0.875 7.1,0.875 12.4,0.875 15,0.875 17.6,0.875 19.677,0.875 25.3,0.875 27.1,0.875 1.1,1 29.3,1 0.9,3.152 29.5,3.152 19.625,3.7 0.9,4.452 18.525,4.9 19.625,5.2 0.9,5.752 16.449,6.518 12.2,6.75 19.625,6.8 0.9,7.1 18.625,7.625 16.459,7.671 0.9,8.3 12.725,8.375 15.494,8.407 11.375,8.55 18.6,8.775 20.125,8.925 22.45,9.3 6.475,9.375 19.225,9.575 0.9,9.652 0.9,11.652 21.925,11.775 29.472,11.965 7.725,12 6.553,12.395 0.9,13.435 29.472,13.435 0.9,14.105 29.472,14.105 7.645,14.427 0.9,15.975 29.472,15.975 7.25,16.025 0.9,16.645 29.472,16.645 0.9,18.515 29.472,18.515 0.9,19.185 29.472,19.185 0.9,21.055 29.472,21.055 14.925,21.25 0.9,21.725 29.472,21.725 16.575,22.2 4.475,22.525 0.9,23.595 29.472,23.595 0.9,24.265 29.472,24.265 0.9,26.135 29.472,26.135 10.795,26.17 0.9,26.805 29.472,26.805 10.1,27 0.9,28.675 29.472,28.675 0.9,29.345 29.472,29.345 0.9,31.215 29.472,31.215 0.9,31.885 29.472,31.885 0.9,33.755 29.472,33.755 0.9,34.425 29.472,34.425 9.6,34.9 10.55,34.9 11.5,34.9 12.45,34.9 13.4,34.9 9.6,35.85 10.55,35.85 11.5,35.85 12.45,35.85 13.4,35.85 0.9,36.252 29.5,36.252 9.6,36.8 10.55,36.8 12.45,36.8 13.4,36.8 9.6,37.75 11.5,37.75 12.45,37.75 13.4,37.75 29.5,38.1 9.6,38.7 10.55,38.7 11.5,38.7 12.45,38.7 13.4,38.7 0.9,39.4 29.5,39.552 20.463,39.6 14.825,40.025 12.995,40.652 13.05,41.475 29.5,41.8 11.325,42.1 28.825,42.45 0.9,42.6 11.699,42.625 15.2,43 29.5,43.3 11.699,43.425 0.9,43.9 14.3,44.075 15.094,44.075 15.889,44.075 16.683,44.075 17.478,44.075 11.413,44.664 29.13,44.825 8.875,44.95 13.228,44.975 17.751,45.301 19.075,45.301 20.5,45.301 21.95,45.301 23.4,45.301 24.85,45.301 1.05,45.5 10.008,45.605 11.75,45.875 13.203,46.275 17.751,46.495 19.075,46.495 20.5,46.495 21.95,46.495 23.4,46.495 24.85,46.495 11.751,46.902 13.201,46.927 17.751,47.663 19.075,47.663 20.5,47.663 21.95,47.663 23.4,47.663 24.85,47.663 11.728,47.943 13.203,47.943 19.075,48.806 20.5,48.806 21.95,48.806 23.4,48.806 24.85,48.806 26.3,48.806 11.751,48.919 12.526,49.348 10.979,49.419 11.754,49.844 19.1,50 20.525,50 21.975,50 23.425,50 24.875,50 26.325,50 5.85,50.125 8.704,50.125 9.829,50.144 4.1,50.2
IMU_SPI_CIPO: U102.3 U104.9 | length 22
  Top Layer w0.1: v1(14.275,21.3) 14.275,21.9 14.713,22.337 14.713,22.712 15.15,23.15 U104.9@15.15,23.675
  Signal Layer 5 w0.1: v1(14.275,21.3) 14.275,22.725 17.65,26.1 17.65,27.7 17.313,28.038 17.313,28.537 18.7,29.925 18.7,32.7 20.775,34.775 20.775,35.975 v1(21.4,36.6)
  Bottom Layer w0.1: U102.3@21.4,35.915 v1(21.4,36.6)
IMU_SPI_COPI: U102.1 U104.24 | length 23
  Top Layer w0.1: U104.24@14.15,27.375 v1(14.15,28.2)
  Signal Layer 4 w0.1: v1(14.15,28.2) 14.675,27.675 20.5,27.675 20.825,27.35 22.25,27.35 22.6,27.7 23.026,27.7 v1(23.463,28.137)
  Signal Layer 5 w0.1: v1(23.463,28.137) 23.463,28.512 23.325,28.65 23.325,29.525 23.975,30.175 23.975,33.15 25.75,34.925 v1(25.75,35.425)
  Bottom Layer w0.1: U102.1@22.2,35.915 25.335,35.915 25.75,35.5 v1(25.75,35.425)
IMU_SPI_CS: R102.2 U102.11 U104.22 | length 16.4
  Top Layer w0.102: U104.22@15.15,27.325 15.15,27.725 15.3,27.875 16.325,27.875 R102.2@16.7,28.25 17.175,28.725 v1(17.175,29.975)
  Signal Layer 5 w0.102: v1(17.175,29.975) 17.175,31.6 17.525,31.95 17.525,33.4 18.05,33.925 18.05,34.1 ; 18.049,34.1 18.049,34.341 ; 18.05,34.342 18.05,34.675 19.05,35.675 19.675,35.675 20.175,36.175 20.175,36.75 20.9,37.475 v1(20.9,38.84)
  Bottom Layer w0.102: v1@20.9,38.89 20.9,38.875 21.8,37.975 U102.11@21.8,37.685
IMU_SPI_SCLK: U102.8 U104.23 | length 14.1
  Top Layer w0.102: U104.23@14.65,27.325 14.65,27.925 v1(14.9,28.175)
  Signal Layer 5 w0.102: v1(14.9,28.175) 15.488,28.763 15.488,30.888 16.075,31.475 16.075,34.3 17.6,35.825 17.6,36.75 18.572,37.722 v1(20.078,37.722)
  Bottom Layer w0.102: v1(20.078,37.722) 20.115,37.685 U102.8@20.6,37.685
MIC_I2S_SCK: U103.3 U111.4 U112.4 | length 58.4
  Signal Layer 4 w0.1: v1(3.647,48.337) 3.05,47.74 3.05,46.35 6.075,43.325 6.775,43.325 10.175,39.925 12.925,39.925 15.95,42.95 17.3,42.95 18.55,44.2 24.5,44.2 25.875,45.575 25.875,47.125 26.275,47.525 28.575,47.525 v1(29.625,46.475)
  Signal Layer 5 w0.1: v1(19.285,31.659) 20.825,33.2 20.825,33.525 22.8,35.5 22.8,38.025 28.55,43.775 28.55,45.4 v1(29.625,46.475)
  Bottom Layer w0.1: U112.4@3.1,47.848 3.158,47.848 v1(3.647,48.337) ; v1(19.285,31.659) 19.7,32.075 U103.3@19.7,32.515 ; U111.4@29.1,47.848 29.625,47.323 v1(29.625,46.475)
MIC_I2S_SD: R150.1 U103.8 U111.6 U112.6 | length 52.6
  Signal Layer 4 w0.1: v1(2.2,43.9) 3.5,42.6 6.825,42.6 10.175,39.25 13.175,39.25 16.175,42.25 17.55,42.25 18.9,43.6 24.775,43.6 26.475,45.3 26.475,45.925 v1(26.875,46.325)
  Signal Layer 5 w0.1: v1(18.45,34.175) 19.75,34.175 20.5,34.925 20.5,36.675 27.425,43.6 27.425,45.825 26.925,46.325 v1(26.875,46.325)
  Bottom Layer w0.1: v1(2.2,43.9) 2.2,44.8 1.6,45.4 R150.1@1.6,46.05 1.6,46.426 U112.6@2.2,47.026 ; v1(18.45,34.175) 18.9,34.175 U103.8@18.9,34.285 ; v1(26.875,46.325) 27.499,46.325 U111.6@28.2,47.026
MIC_I2S_WS: U103.11 U111.1 U112.1 | length 52.9
  Signal Layer 4 w0.1: v1(1.5,44.4) 2.35,44.4 3.85,42.9 6.85,42.9 10.175,39.575 13.05,39.575 16.05,42.575 17.4,42.575 18.725,43.9 24.625,43.9 26.175,45.45 26.175,46.6 v1(26.6,47.025)
  Signal Layer 5 w0.1: v1(20.975,34.3) 20.975,35.35 22.5,36.875 22.5,38.175 27.875,43.55 27.875,46.3 27.15,47.025 v1(26.6,47.025)
  Bottom Layer w0.1: U112.1@1.3,47.026 0.6,46.326 0.6,45.3 v1(1.5,44.4) ; U103.11@20.1,34.285 20.1,34.55 20.325,34.775 20.875,34.775 20.975,34.675 v1(20.975,34.3) ; v1(26.6,47.025) 26.601,47.026 U111.1@27.3,47.026
N16783813: D900.3 L901.1 P900.1 | length 2.1
  Top Layer w0.305: L901.1@12.7,5.9 D900.3@13.575,5.9
  Top Layer w0.4: P900.1@13.695,4.55 D900.3@13.695,5.78
N16783896: R908.1 R909.2 U902.5 | length 1.3
  Bottom Layer w0.127: R909.2@4.325,48.9 U902.5@5.675,48.9
N16783941: R907.1 U902.7 | length 0.8
  Bottom Layer w0.127: U902.7@6.675,48.9 6.675,49.425 6.794,49.544 6.794,49.554 6.89,49.65 R907.1@6.9,49.65
N16783963: C918.1 U902.6 | length 0.8
  Bottom Layer w0.1: U902.6@6.175,48.9 6.175,49.575 C918.1@6.25,49.65
N16784657: C921.1 P901.1 P902.2 Q901.3 Q901.8 | length 145.3
  Signal Layer 3 w0.7: v1(18.1,24.875) v1(18.8,24.875) 19.8,24.875 21.125,23.55 21.125,20.525 22.8,18.85 23.95,18.85 25.4,17.4 v1(25.4,15.45) 25.425,15.45 v1(25.95,14.925)
  Signal Layer 6 w0.5: v1(25.4,15.45) 25.925,14.925 v1(25.95,14.925)
  Signal Layer 6 w0.6: 4.25,27.325 3.7,27.875 3.7,36.175 5.65,38.125 6.65,38.125 7.05,38.525 7.05,38.975 6.625,39.4 6.625,40.9 v1(6.65,40.925) 6.775,41.05 6.775,41.55 v1@6.512,41.812
  Signal Layer 6 w0.7: v1(2.285,5.69) v1(2.285,8.69) 2.285,9.11 3.84,10.665 v1(4.085,10.665) ; v1(3.31,4.54) 4.735,5.965 v1(4.735,10.665) ; 4.25,27.325 4.3,27.325 5.325,26.3 6.075,26.3 6.65,25.725 6.65,21.75 3.8,18.9 3.8,10.95 v1(4.085,10.665) ; v1(24.425,4.225) 24.925,5.25 24.925,9.9 24.202,11.191 24.162,11.262 ; 25.075,7.5 v1@29.525,7.5 ; 25.575,15.25 26.2,14.625 26.2,13 25.7,12.5 25.4,12.5 24.162,11.262 ; v1(4.085,10.665) v1(4.735,10.665) ; v1(4.735,10.665) 22.19,10.665 22.575,11.05 v1(23.95,11.05) 24.162,11.262
  Bottom Layer w0.3: v1(6.5,41.725) 6.65,41.875 6.65,42.075 6.85,42.275 Q901.8@7.184,42.275 Q901.8@7,42.092 ; v1(6.5,41.725) 6.6,41.625 6.6,40.975 v1(6.65,40.925) v1@6.817,41.092 ; v1(6.5,41.725) 6.634,41.725 6.817,41.908 ; v1@6.817,41.092 6.817,41.908 ; v1@6.817,41.092 7,41.275 Q901.8@7,42.092 ; 6.817,41.908 Q901.8@7,42.092
  Bottom Layer w0.635: v1(2.285,5.69) P901.1@2.888,5.69 ; v1(2.285,8.69) 2.888,8.69 P901.1@4.063,7.515 ; v1(3.31,4.54) P901.1@3.31,6.987 ; P901.1@3.535,6.987 P901.1@4.063,7.515 ; P901.1@5.138,7.19 P901.1@4.438,7.89 ; P901.1@4.063,7.515 P901.1@4.438,7.89 ; P901.1@4.063,7.515 P901.1@4.063,9.415 ; P901.1@4.063,9.415 4.41,9.762 4.41,10.665 ; P901.1@4.063,9.415 4.063,10.643 v1(4.085,10.665) 4.41,10.665 ; 4.41,10.665 v1(4.735,10.665) 4.735,8.187 P901.1@4.438,7.89
  Bottom Layer w0.7: P902.2@16.825,24.875 v1(18.1,24.875) v1(18.8,24.875) ; v1(23.95,11.05) 24.45,10.9 ; v1(24.425,4.225) P901.1@25.922,7.5 ; C921.1@25.4,16.6 v1(25.4,15.45) 26.225,14.625 26.225,13.075 24.45,11.3 24.45,10.9 ; v1@29.5,7.5 P901.1@25.922,7.5 ; 24.45,10.9 P901.1@25.023,9.577 ; P901.1@25.023,9.577 25.922,8.678 P901.1@25.922,7.5 ; P901.1@25.023,9.577 P901.1@25.922,7.5
  other v1: 29.625,7.5
N16820078: C3.1 L1.1 U1.16 | length 2
  Top Layer w0.127: U1.16@12.503,39.732 12.503,41.049 L1.1@12.503,41.71
N16820097: C4.1 L1.2 L2.1 | length 1.3
  Top Layer w0.127: L1.2@12.503,42.235 12.503,42.784 L2.1@12.503,43.501
N16820130: C2.1 C5.1 L2.2 | length 1.2
  Top Layer w0.127: L2.2@12.503,44.026 12.503,44.673 C2.1@12.503,45.212
N16820670: C11.1 C12.1 L4.2 U1.14 | length 2.7
  Top Layer w0.22: U1.14@13.3,39.735 13.3,40.225 C12.1@13.825,40.75
  Top Layer w0.3: C12.1@13.825,40.75 C11.1@14.475,40.75 14.85,41.125 L4.2@15.18,41.125
N16820694: C18.1 C19.1 L5.2 U1.17 | length 3.4
  Top Layer w0.22: 12.011,40.914 12.1,40.825 U1.17@12.1,39.735
  Top Layer w0.3: L5.2@9.97,41.305 10.445,41.305 10.675,41.075 11.25,41.075 11.275,41.05 11.412,41.05 11.416,41.054 11.834,41.054 11.838,41.05 11.875,41.05 12.011,40.914
N16821218: C17.1 U1.36 | length 0.9
  Top Layer w0.2: C17.1@7.75,34.375 7.975,34.6 U1.36@8.565,34.6
N16822182: C20.1 C21.1 R6.2 U1.41 | length 4.7
  Top Layer w0.2: C20.1@10.8,30.825 11.1,31.125 11.1,31.475 11.315,31.69 11.315,32.189 11.325,32.199 11.325,32.25 11.575,32.5 C21.1@11.675,32.5 10.9,33.275 U1.41@10.9,33.865
  Top Layer w0.3: R6.2@10.675,29.975 10.675,30.7 C20.1@10.8,30.825
N16822845: R1.2 SW1.3 SW1.4 | length 5.9
  Top Layer w0.1: R1.2@21.6,39.4 21.6,38.55 SW1.4@21.675,38.475 21.675,38.3 20.75,37.375 20.75,35.475 21.675,34.55 SW1.3@21.675,34.325
N16942953: C106.1 U104.10 | length 0.9
  Top Layer w0.25: U104.10@15.65,23.525 15.65,23.175 C106.1@16.025,22.8
N16944331: R109.2 TP1.1 U105.3 | length 4.1
  Top Layer w0.1: U105.3@22.55,30.475 22.5,30.425 R109.2@22.5,29.7 23.525,29.7 v1(24.5,28.725)
  Bottom Layer w0.1: TP1.1@24.5,27.8 v1(24.5,28.725)
N16944525: R112.2 TP2.1 U107.5 | length 2.7
  Top Layer w0.2: R112.2@26.85,40.75 U107.5@26.85,39.9 26.925,39.975 v1(27.75,39.975)
  Bottom Layer w0.2: TP2.1@26.8,40 26.825,39.975 v1(27.75,39.975)
N17008241: C900.1 U900.J13 | length 1.1
  Bottom Layer w0.2: U900.J13@10.25,22.5 10.5,22.25 C900.1@10.5,21.5
N17008263: C903.1 C904.1 C905.1 L900.2 U900.M9 U900.M10 U900.N11 | length 5.3
  Bottom Layer w0.1: 12.025,24.7 12.075,24.75 12.45,24.75
  Bottom Layer w0.2: 12.025,24.7 11.95,24.7 U900.M9@11.75,24.5 U900.M10@11.75,24 U900.N11@12.25,23.5 12.775,22.975 13.25,22.975 C904.1@13.275,22.95 ; 12.45,24.75 12.475,24.775 13,24.775 ; 13.025,24.775 13.125,24.775 C905.1@13.2,24.85
  Bottom Layer w0.3: C904.1@13.275,22.95 13.28,22.945 L900.2@13.85,22.945 14.43,22.945 C903.1@14.525,22.85 ; C903.1@14.57,22.87 C903.1@14.575,22.875
N17151320: L8.2 R6.1 | length 0.6
  Top Layer w0.3: R6.1@11.275,29.975 L8.2@11.905,29.975
N17172364: L6.1 U1.37
N17191783: LED900.2 R905.2 | length 0.8
  Top Layer w0.2: LED900.2@18,6.95 18.45,6.95 R905.2@18.7,6.7
N17218868: R141.1 SW100.3 SW100.4 | length 5.4
  Top Layer w0.1: SW100.3@24.225,1.125 24.45,1.35 28.15,1.35 SW100.4@28.375,1.125 28.525,1.125 R141.1@29.2,1.8
N17219122: R144.1 SW101.3 SW101.4 | length 5.4
  Top Layer w0.1: R144.1@1.2,1.8 1.875,1.125 SW101.3@2.025,1.125 2.25,1.35 5.95,1.35 SW101.4@6.175,1.125
N17219358: LED100.4 R135.1 | length 1.2
  Top Layer w0.2: R135.1@14,19.55 14.775,18.775 LED100.4@14.775,18.675
N17219362: LED100.3 R136.1 | length 0.8
  Top Layer w0.2: LED100.3@15.625,18.675 16.425,18.675 R136.1@16.45,18.65
N17219366: LED100.2 R137.1 | length 0.8
  Top Layer w0.2: LED100.2@15.625,19.525 16.425,19.525 R137.1@16.45,19.55
N17219671: P100.1 R129.1 | length 1.2
  Top Layer w0.2: P100.1@4.2,39.4 4.3,39.5 R129.1@5.35,39.5
N17314136: Q200.5 R206.2 R207.1 | length 1.8
  Bottom Layer w0.125: Q200.5@22.95,21.1 23.95,21.1 R206.2@23.95,20.25
N17314162: Q200.6 R212.1 | length 2.6
  Bottom Layer w0.125: Q200.6@22.95,20.6 23.15,20.6 23.3,20.45 23.3,19.2 R212.1@23.95,18.55
N17314928: Q200.2 Q200.3 R208.2 | length 2.9
  Bottom Layer w0.102: R208.2@21.65,19.7 21.175,20.175 21.175,21.1 ; Q200.2@21.65,21.1 21.175,21.1 ; Q200.3@21.65,21.6 21.425,21.6 21.175,21.35 21.175,21.1
N17328899: Q200.4 R210.1 | length 1.1
  Bottom Layer w0.125: Q200.4@22.95,21.6 23.6,21.6 R210.1@23.95,21.95
N17329050: C115.1 D101.1 R114.1 R116.2 | length 2.8
  Top Layer w0.2: D101.1@4.65,44.5 4.65,43.4 R116.2@4.7,43.35 R114.1@6.3,43.35
N17344672: C2.2 C6.1 L3.1 | length 2.2
  Top Layer w0.381: C2.2@12.462,45.782 12.467,45.786 12.467,47.42 C6.1@12.462,47.416 ; C6.1@12.462,47.42 L3.1@12.462,47.983
N17345163: ANT1.1 L3.2 | length 1.4
  Top Layer w0.381: L3.2@12.488,48.63 ANT1.1@13.85,48.63
N17347250: C154.1 R158.2 U112.5 | length 1.7
  Bottom Layer w0.3: R158.2@2.2,46.05 C154.1@2.825,46.05 2.825,46.751 U112.5@3.1,47.026
N17347298: L151.2 R157.1 | length 0.6
  Bottom Layer w0.3: L151.2@27.97,45.3 R157.1@28.55,45.3
N17347312: L152.2 R158.1 | length 0.6
  Bottom Layer w0.3: R158.1@2.2,45.45 L152.2@2.83,45.45
N17359976: TP3.1 U106.7 | length 4
  Top Layer w0.1: v1(23.55,17.75) 23.658,17.75 U106.7@24.25,18.343
  Bottom Layer w0.1: TP3.1@20.8,17.8 21.8,17.8 22.1,17.5 23.3,17.5 v1(23.55,17.75) v1@23.625,17.675
N17374949: U1.11 X1.3 | length 3.4
  Top Layer w0.1: U1.11@14.435,38.6 14.775,38.6 15.5,39.325 16.475,39.325 X1.3@17.2,38.6
N17374973: U1.12 X1.1 | length 2.1
  Top Layer w0.1: U1.12@14.435,39 14.775,39 15.425,39.65 15.75,39.65 X1.1@16.1,40
N17389062: Q902.2 R916.2 R917.1 R934.1 | length 2
  Bottom Layer w0.2: R934.1@4.783,40.368 4.79,40.375 R917.1@4.8,40.375 5,40.375 ; Q902.2@5,41.675 5,40.375 ; R916.2@5.475,40.375 5,40.375
N17389066: R934.2 TP900.1 | length 1.9
  Bottom Layer w0.2: R934.2@4.801,39.768 4.801,38.199 TP900.1@5,38
N17389104: Q902.5 Q902.6 R918.1 | length 1.9
  Bottom Layer w0.152: Q902.5@5,42.975 5,43.725 5.006,43.731 5.006,43.741 5.09,43.825 R918.1@5.1,43.825 5.11,43.825 5.194,43.741 5.194,43.731 5.5,43.425 Q902.6@5.5,42.975
SENSOR_I2C_SCL: R107.2 U101.3 U105.5 U106.2 U107.3 U108.6 | length 52.9
  Top Layer w0.1: U105.5@21.9,32.125 R107.2@21.9,32.95 21.925,32.975 22.275,32.975 v1(22.85,33.55) ; v1(22.3,21.1) 22.9,20.5 23.108,20.5 U106.2@23.75,19.857 ; v1(25.25,14.043) 24.675,13.468 24.675,10.575 26.4,8.85 U108.6@27,8.85 ; U107.3@28.75,37.5 v1(28.75,38.375)
  Signal Layer 5 w0.1: v1(25.25,14.043) 24.1,15.193 24.1,19.3 v1(22.3,21.1) 20.65,22.75 20.65,28.8 22.825,30.975 22.825,32.175 23.2,32.55 23.2,33.2 v1(22.85,33.55) 27.025,37.725 28.1,37.725 v1(28.75,38.375)
  Bottom Layer w0.1: U101.3@19.7,40.315 19.7,39.525 20.125,39.1 20.55,39.1 20.725,39.275 21.6,39.275 22.925,37.95 28.325,37.95 v1(28.75,38.375)
SENSOR_I2C_SDA: R108.2 U101.8 U105.2 U106.4 U107.1 U108.1 | length 56.5
  Top Layer w0.1: v1(21.6,18.95) 21.675,19.025 23.168,19.025 U106.4@23.243,19.1 ; R108.2@21.9,29.7 U105.2@21.9,30.475 22,30.575 22,31.075 v1(22.35,31.425) ; v1(23.5,14.5) 24.475,13.525 24.475,10.475 26.35,8.6 26.35,6.775 27,6.125 U108.1@27,5.95 ; U107.1@26.85,37.5 v1(26.85,38.975)
  Signal Layer 5 w0.1: v1(23.5,14.5) 23.5,17.05 v1(21.6,18.95) 20.275,20.275 20.275,29.35 v1(22.35,31.425) 22.35,32.375 22.175,32.55 22.175,33 22.45,33.275 22.45,33.975 26.85,38.375 v1(26.85,38.975)
  Bottom Layer w0.1: U101.8@18.9,42.085 18.54,42.085 18.325,42.3 18.325,43.125 18.65,43.45 20.725,43.45 21.375,42.8 21.375,42.225 21.812,41.788 21.812,41.063 23.9,38.975 v1(26.85,38.975)
USB_PGOOD: R929.1 U900.E1 | length 15.2
  Signal Layer 5 w0.1: v1(6.075,41.25) 6.075,40.4 5.8,40.125 5.8,37.975 6.4,37.375 6.4,32.579 v1(8.327,30.652)
  Bottom Layer w0.1: v1(6.075,41.25) 6.075,41.975 6.15,42.05 6.15,42.2 R929.1@6.225,42.275 ; U900.E1@8.25,28.5 8,28.75 8,30.325 v1(8.327,30.652)
V_ADC: R114.2 U101.11 | length 20.8
  Top Layer w0.2: R114.2@6.3,42.45 8,42.45 v1@8.925,43.375
  Signal Layer 6 w0.2: v1@8.925,43.375 8.25,42.7 8.25,41.45 9.9,39.8 12.925,39.8 16.6,43.475 19.885,43.475 v1(20.45,42.91)
  Bottom Layer w0.2: U101.11@20.1,42.085 20.1,42.56 v1(20.45,42.91)
  other v1: 8.95,43.375
VDCDC: C7.1 C13.1 L4.1 L5.1 L6.2 U1.40 | length 36.6
  Top Layer w0.2: v1@10.438,32.563 10.5,32.5 C13.1@10.95,32.5 ; U1.40@10.5,33.865 10.5,33.25 10.95,32.8 C13.1@10.95,32.563
  Top Layer w0.3: v1@9.4,41.95 v1@9.43,41.92
  Top Layer w0.35: v1@9.43,41.92 9.43,41.93 v1(9.45,41.95)
  Top Layer w0.37: L5.1@9.43,41.375 9.43,41.755 v1@9.45,41.775
  Top Layer w0.5: v1@9.45,41.775 v1(9.45,41.95) v1(9.45,42.6) ; L4.1@15.825,41.125 v1(16.2,41.5) v1(16.825,41.5)
  Top Layer w0.7: v1(5.975,31.55) v1(6.6,31.55) C7.1@7.2,31.55 7.175,31.575 L6.2@7.175,32.75
  Signal Layer 3 w0.5: 9.425,41.35 9.45,41.375 v1(9.45,41.95) v1(9.45,42.6)
  Signal Layer 3 w0.7: v1(5.975,31.55) v1(6.6,31.55) 6.975,31.55 9.05,33.625 9.05,34.225 8.75,34.525 8.75,38.875 9.25,39.375 9.25,41.175 9.425,41.35
  Signal Layer 5 w0.5: 9.4,41.3 9.45,41.35 v1(9.45,41.95) v1(9.45,42.6)
  Signal Layer 5 w0.7: 9.4,41.3 9.15,41.05 9.15,40.55 10,39.7 13.075,39.7 14.875,41.5 v1(16.2,41.5) v1(16.825,41.5)
  Signal Layer 6 w0.7: v1(5.975,31.55) v1(6.6,31.55) 6.925,31.55 8.55,33.175 9.975,33.175 10.438,32.712 v1@10.438,32.6
  other v1: 10.438,32.538
VDD_MIC: L151.1 L152.1 R930.2 U103.1 | length 70
  Signal Layer 5 w0.3: v1(19.725,18.4) 19.725,30.675 19.825,30.775 v1(19.825,31.325) 21.225,32.725 21.225,33.375 23.1,35.25 23.1,37.725 27.575,42.2 v1(27.925,42.2)
  Signal Layer 6 w0.2: v1(3.4,44.95) 4.25,44.95 9.9,39.3 13.05,39.3 16.15,42.4 20.6,42.4 21.9,43.7 25.65,43.7 v1(26.85,44.9)
  Signal Layer 6 w0.3: v1(12.575,20.5) 12.775,20.3 12.775,20.293 13.068,20 13.075,20 15.025,18.05 19.375,18.05 v1(19.725,18.4)
  Bottom Layer w0.2: v1@19.825,31.35 20.5,32.025 U103.1@20.5,32.515
  Bottom Layer w0.3: L152.1@3.37,45.45 3.37,44.98 v1(3.4,44.95) ; L151.1@27.25,45.3 v1(26.85,44.9) 26.85,43.275 v1(27.925,42.2)
  Bottom Layer w0.305: v1(12.575,20.5) 12.575,20.55 12.625,20.6 R930.2@12.625,20.975
VDD_MIC_FILT: C156.1 R157.2 U111.2 U111.5 | length 3.9
  Bottom Layer w0.2: U111.2@27.3,47.848 28.227,47.848 29.049,47.026 U111.5@29.1,47.026
  Bottom Layer w0.3: R157.2@28.55,45.9 28.575,45.875 C156.1@29.1,45.875 U111.5@29.1,47.026
VDD_SENSOR: C104.1 C105.1 C110.1 C111.1 C113.1 C114.1 R102.1 R103.1 R107.1 R108.1 R109.1 R112.1 R931.2 U101.1 U104.8 U104.13 U105.6 U106.1 U106.5 U106.6 U106.10 U107.4 U108.5 | length 102.4
  Top Layer w0.2: v1(21.5,28.325) 21.9,28.725 R108.1@21.9,29.1 R109.1@22.5,29.1 ; U106.5@23.243,18.6 23.325,18.6 23.563,18.838 ; U106.6@23.75,18.343 23.75,18.65 23.563,18.838 ; U106.10@24.758,19.6 25.575,19.6 C111.1@25.6,19.575 ; v1(25.6,20.075) 24.468,20.075 U106.1@24.25,19.857 24.25,19.525 23.563,18.838
  Top Layer w0.25: v1(13.95,20.7) 13.35,21.3 13.35,22.1 13.6,22.35 14.25,22.35 14.375,22.475 C104.1@14.375,22.75 ; C104.1@14.375,22.8 14.65,23.075 U104.8@14.65,23.525 ; U104.13@17.375,24.25 17.625,24.25 ; 17.75,23.15 17.625,23.275 ; R103.1@17.85,22.8 17.85,23.05 17.625,23.275 ; C105.1@18.225,24.25 C105.1@18.175,24.25 17.625,24.25 ; 17.625,23.275 17.625,24.25
  Top Layer w0.3: R102.1@17.3,28.25 v1(17.8,28.25) v1@17.85,28.25 ; R103.1@17.85,22.8 v1(18.35,22.8) v1@18.4,22.8 ; C110.1@20.35,32.075 21.2,32.075 U105.6@21.25,32.125 ; R107.1@21.3,32.95 21.3,32.175 U105.6@21.25,32.125 ; v1(21.5,31.35) 21.25,31.6 U105.6@21.25,32.125 ; C111.1@25.6,19.575 v1(25.6,20.075) ; R112.1@27.45,40.775 v1(27.45,41.275) ; v1(27.8,9.7) C114.1@28.325,9.7 28.325,9.325 28,9 U108.5@28,8.85 ; U107.4@28.75,39.9 28.825,39.975 28.825,40.75 v1(29.325,40.75)
  Signal Layer 3 w0.3: 17.3,28.2 16.6,27.5 16.6,24.35 18.1,22.85 18.3,22.85 v1(18.35,22.8) ; 17.3,28.25 v1(17.8,28.25) ; v1(21.5,28.325) v1(21.5,31.35) ; v1(27.8,9.7) 27.8,9.1 27.5,8.8 26.1,8.8 24.575,10.325 24.575,12.575 v1(25.25,13.25) 26.725,14.725 26.725,18.95 v1(25.6,20.075) 25.1,20.575 25.1,24.6 v1(26.3,25.8) 26.775,26.275 26.775,38.15 29.325,40.7 v1(29.325,40.75)
  Signal Layer 6 w0.3: v1(13.95,20.7) 16.3,20.7 17.05,21.45 17.575,21.45 18.35,22.225 v1(18.35,22.8) 22.875,22.8 v1(25.6,20.075) ; v1(21.5,28.325) 21.425,28.25 21.425,27.4 22.2,26.625 25.475,26.625 v1(26.3,25.8)
  Bottom Layer w0.2: U101.1@20.5,40.315 20.835,40.315 21.15,40 21.55,40 23.2,38.35 27.05,38.35 28.7,40 ; v1@27.45,41.25 28.7,40 ; v1(29.325,40.75) 29.325,40.625 28.7,40
  Bottom Layer w0.3: R931.2@17.1,28.1 17.65,28.1 v1(17.8,28.25)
